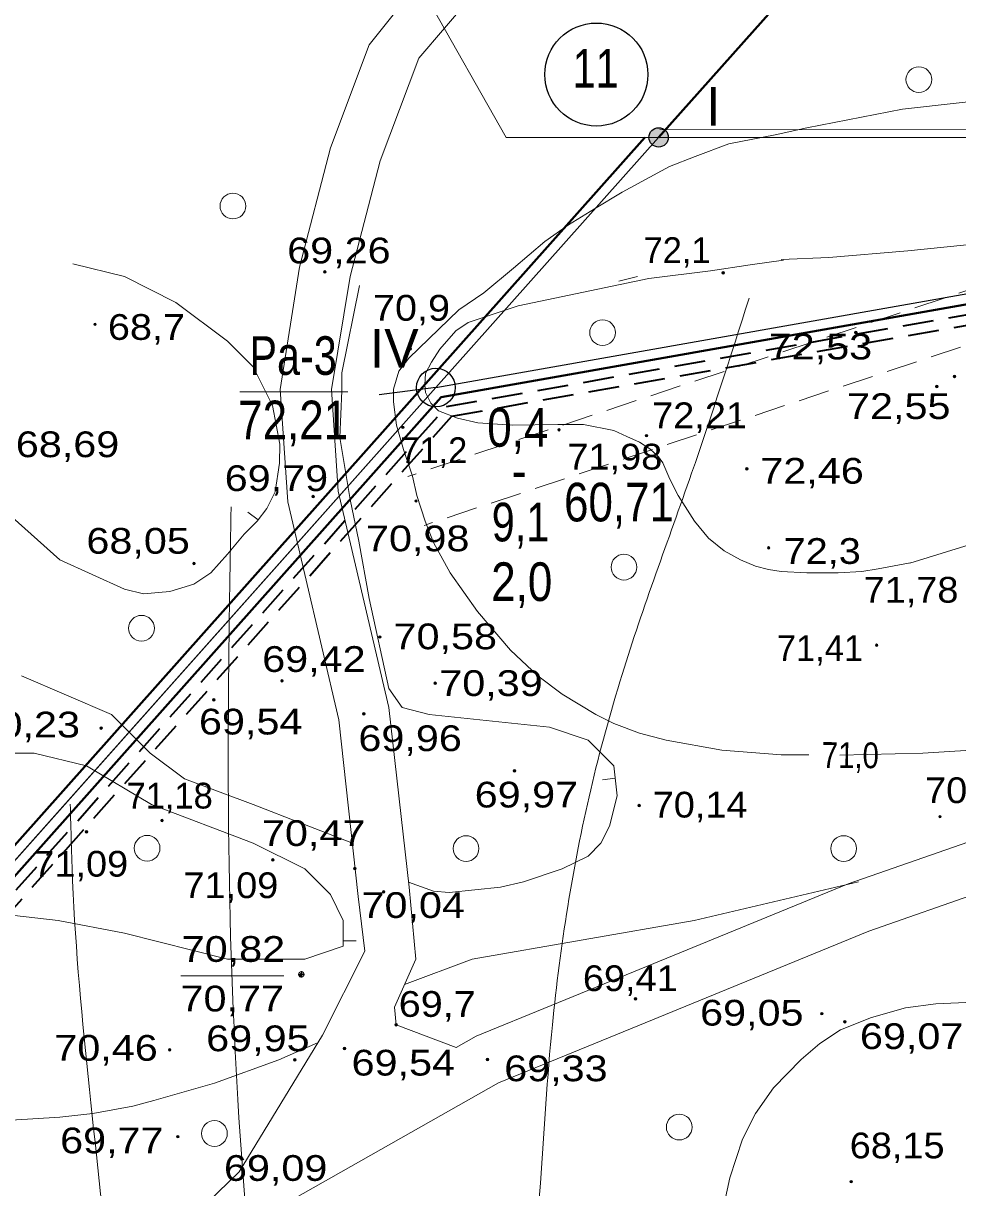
# Model space of a CAD drawing. Extents: x 628176 to 629009, y 6439913 to 6440496.
# Drawn here: x 628361.2 to 628433.7, y 6440336.2 to 6440426.7 of the extents above; entities that cross this region are included whole.
import ezdxf
from ezdxf.enums import TextEntityAlignment as Align

# ---------------------------------------------------------------- set-up
doc = ezdxf.new("R2010")
doc.units = 0
doc.header["$LTSCALE"] = 0.8
doc.header["$PDMODE"] = 32
doc.header["$PDSIZE"] = 0.4
doc.linetypes.add('MEDIUM_DASHED', pattern=[4.5, 3, -1.5])
for name, color, linetype, lineweight in [('1', 7, 'Continuous', 13), ('10', 7, 'Continuous', 25), ('11', 7, 'Continuous', 13), ('12', 7, 'Continuous', 13), ('14', 7, 'Continuous', 25), ('16', 7, 'Continuous', 13), ('20', 7, 'Continuous', 40), ('21', 7, 'MEDIUM_DASHED', 35), ('3', 7, 'Continuous', 13), ('6', 7, 'Continuous', 13)]:
    doc.layers.add(name, color=color, linetype=linetype, lineweight=lineweight)

msp = doc.modelspace()

# ---------------------------------------------------------------- hatches: boundary and pattern name
at = {"layer": '1'}
for points in [[(628384.6556, 6440407.3657, 1), (628384.4556, 6440407.3657, 1)], [(628415.5893, 6440407.2985, 1), (628415.3893, 6440407.2985, 1)], [(628366.8202, 6440403.2956, 1), (628366.6202, 6440403.2956, 1)], [(628425.888, 6440402.6645, 1), (628425.688, 6440402.6645, 1)], [(628391.2986, 6440401.3946, 1), (628391.0986, 6440401.3946, 1)], [(628433.5561, 6440399.2515, 1), (628433.3561, 6440399.2515, 1)], [(628432.1769, 6440398.468, 1), (628431.9769, 6440398.468, 1)], [(628390.7286, 6440395.2981, 1), (628390.5286, 6440395.2981, 1)], [(628402.847, 6440395.112, 1), (628402.647, 6440395.112, 1)], [(628409.6313, 6440394.6528, 1), (628409.4313, 6440394.6528, 1)], [(628417.4364, 6440392.0781, 1), (628417.2364, 6440392.0781, 1)], [(628383.7494, 6440389.9172, 1), (628383.5494, 6440389.9172, 1)], [(628391.7433, 6440389.5751, 1), (628391.5433, 6440389.5751, 1)], [(628419.1251, 6440385.9317, 1), (628418.9251, 6440385.9317, 1)], [(628374.5019, 6440384.7205, 1), (628374.3019, 6440384.7205, 1)], [(628388.9275, 6440379.0094, 1), (628388.7275, 6440379.0094, 1)], [(628427.5111, 6440378.3701, 1), (628427.3111, 6440378.3701, 1)], [(628381.3358, 6440375.6103, 1), (628381.1358, 6440375.6103, 1)], [(628393.2398, 6440375.419, 1), (628393.0398, 6440375.419, 1)], [(628376.0368, 6440374.1368, 1), (628375.8368, 6440374.1368, 1)], [(628387.6971, 6440373.0504, 1), (628387.4971, 6440373.0504, 1)], [(628367.2906, 6440371.9388, 1), (628367.0906, 6440371.9388, 1)], [(628399.3871, 6440368.615, 1), (628399.1871, 6440368.615, 1)], [(628409.0693, 6440365.9186, 1), (628408.8693, 6440365.9186, 1)], [(628372.0228, 6440364.7648, 1), (628371.8228, 6440364.7648, 1)], [(628432.4266, 6440365.061, 1), (628432.2266, 6440365.061, 1)], [(628366.1523, 6440363.8858, 1), (628365.9523, 6440363.8858, 1)], [(628380.6172, 6440361.6969, 1), (628380.4172, 6440361.6969, 1)], [(628386.9911, 6440361.0246, 1), (628386.7911, 6440361.0246, 1)], [(628389.233, 6440359.2215, 1), (628389.033, 6440359.2215, 1)], [(628382.7615, 6440352.6918, 1), (628382.5615, 6440352.6918, 1)], [(628382.8372, 6440352.8118, 1), (628382.6372, 6440352.8118, 1)], [(628408.7874, 6440350.9089, 1), (628408.5874, 6440350.9089, 1)], [(628423.26, 6440349.7561, 1), (628423.06, 6440349.7561, 1)], [(628425.0383, 6440349.1318, 1), (628424.8383, 6440349.1318, 1)], [(628390.1948, 6440348.8964, 1), (628389.9948, 6440348.8964, 1)], [(628372.6184, 6440346.9498, 1), (628372.4184, 6440346.9498, 1)], [(628386.1926, 6440347.0472, 1), (628385.9926, 6440347.0472, 1)], [(628397.2867, 6440346.1959, 1), (628397.0867, 6440346.1959, 1)], [(628382.3265, 6440346.1721, 1), (628382.1265, 6440346.1721, 1)], [(628373.2407, 6440340.2028, 1), (628373.0407, 6440340.2028, 1)], [(628425.5388, 6440336.7091, 1), (628425.3388, 6440336.7091, 1)]]:
    msp.add_hatch(color=256, dxfattribs=at).paths.add_polyline_path(points)
at = {"layer": '10'}
msp.add_hatch(color=256, dxfattribs=at).paths.add_polyline_path([(628411.2339, 6440417.8164, 1), (628409.7339, 6440417.8164, 1)])

# ---------------------------------------------------------------- linework, layer by layer
at = {"layer": '1'}
for p, q in [((628388, 6440425), (628396, 6440435)), ((628399.08, 6440432.45), (628391.87, 6440423.98)), ((628386.52, 6440407), (628385.09, 6440398.24)), ((628385.09, 6440398.24), (628385.6, 6440390.34)), ((628385.6, 6440390.34), (628389.54, 6440373.53)), ((628381.69, 6440389.5), (628385.66, 6440372.57)), ((628389.54, 6440373.53), (628391.1, 6440359.57)), ((628385.66, 6440372.57), (628387.16, 6440358.87)), ((628447.23, 6440367.53), (628425.19, 6440359.83)), ((628448.37, 6440363.69), (628426.81, 6440356.17)), ((628391.1, 6440359.57), (628391.62, 6440354)), ((628425.19, 6440359.83), (628407.95, 6440352.77)), ((628387.16, 6440358.87), (628387.68, 6440354.6)), ((628426.81, 6440356.17), (628409.43, 6440349.05)), ((628387.68, 6440354.6), (628384.39, 6440348.09)), ((628391.62, 6440354), (628389.97, 6440350.27)), ((628373.37, 6440352.69), (628381.37, 6440352.69)), ((628382.74, 6440352.81), (628382.49, 6440352.81)), ((628382.74, 6440352.81), (628382.74, 6440353.06)), ((628382.74, 6440352.81), (628382.74, 6440352.56)), ((628382.74, 6440352.81), (628382.99, 6440352.81)), ((628407.95, 6440352.77), (628396.32, 6440348)), ((628389.97, 6440350.27), (628390.09, 6440348.9)), ((628409.43, 6440349.05), (628398.05, 6440344.39)), ((628390.09, 6440348.9), (628394.77, 6440347.12)), ((628384.39, 6440348.09), (628377.9, 6440337.48)), ((628394.77, 6440347.12), (628396.32, 6440348)), ((628398.05, 6440344.39), (628380.54, 6440334.48)), ((628372.24, 6440332), (628377.9, 6440337.48))]:
    msp.add_line(p, q, dxfattribs=at)
at = {"layer": '1', "linetype": 'MEDIUM_DASHED'}
for p, q in [((628439.49, 6440407.6), (628391.01, 6440391.47)), ((628440.75, 6440403.8), (628392.27, 6440387.68))]:
    msp.add_line(p, q, dxfattribs=at)
at = {"layer": '1'}
for points in [[(628382.59, 6440407.73), (628385, 6440417), (628388, 6440425)], [(628391.87, 6440423.98), (628388.87, 6440416), (628386.52, 6440407)], [(628382.59, 6440407.73), (628381.09, 6440398.24), (628381.69, 6440389.5)]]:
    msp.add_lwpolyline(points, dxfattribs=at)
for centre, radius in [((628430.688, 6440422.3012), 1), ((628377.428, 6440412.4844), 1), ((628384.5556, 6440407.3657), 0.1), ((628415.4893, 6440407.2985), 0.1), ((628366.7202, 6440403.2956), 0.1), ((628406.128, 6440402.6533), 1), ((628425.788, 6440402.6645), 0.1), ((628391.1986, 6440401.3946), 0.1), ((628433.4561, 6440399.2515), 0.1), ((628432.0769, 6440398.468), 0.1), ((628390.6286, 6440395.2981), 0.1), ((628402.747, 6440395.112), 0.1), ((628409.5313, 6440394.6528), 0.1), ((628417.3364, 6440392.0781), 0.1), ((628383.6494, 6440389.9172), 0.1), ((628391.6433, 6440389.5751), 0.1), ((628407.7893, 6440384.4394), 1), ((628419.0251, 6440385.9317), 0.1), ((628374.4019, 6440384.7205), 0.1), ((628370.3308, 6440379.6903), 1), ((628388.8275, 6440379.0094), 0.1), ((628427.4111, 6440378.3701), 0.1), ((628381.2358, 6440375.6103), 0.1), ((628393.1398, 6440375.419), 0.1), ((628375.9368, 6440374.1368), 0.1), ((628387.5971, 6440373.0504), 0.1), ((628367.1906, 6440371.9388), 0.1), ((628399.2871, 6440368.615), 0.1), ((628408.9693, 6440365.9186), 0.1), ((628371.9228, 6440364.7648), 0.1), ((628432.3266, 6440365.061), 0.1), ((628366.0523, 6440363.8858), 0.1), ((628370.7645, 6440362.6041), 1), ((628395.5275, 6440362.5813), 1), ((628424.8493, 6440362.5813), 1), ((628380.5172, 6440361.6969), 0.1), ((628386.8911, 6440361.0246), 0.1), ((628389.133, 6440359.2215), 0.1), ((628382.6615, 6440352.6918), 0.1), ((628382.7372, 6440352.8118), 0.1), ((628408.6874, 6440350.9089), 0.1), ((628423.16, 6440349.7561), 0.1), ((628424.9383, 6440349.1318), 0.1), ((628390.0948, 6440348.8964), 0.1), ((628372.5184, 6440346.9498), 0.1), ((628386.0926, 6440347.0472), 0.1), ((628397.1867, 6440346.1959), 0.1), ((628382.2265, 6440346.1721), 0.1), ((628412.0851, 6440340.9481), 1), ((628375.9918, 6440340.4503), 1), ((628373.1407, 6440340.2028), 0.1), ((628425.4388, 6440336.7091), 0.1)]:
    msp.add_circle(centre, radius, dxfattribs=at)
at = {"layer": '10'}
for centre, radius in [((628405.6476, 6440422.6988), 4), ((628410.4839, 6440417.8164), 0.75)]:
    msp.add_circle(centre, radius, dxfattribs=at)
at = {"layer": '11'}
for points in [[(628393.19, 6440398.39), (628410.48, 6440417.82), (628464.14, 6440417.8), (628544.36, 6440425.1), (628575.19, 6440427.91), (628595.11, 6440426.87)], [(628393.19, 6440398.39), (628479.31, 6440413.61), (628544.36, 6440425.1)], [(628497.5, 6440118.54), (628474.19, 6440080.39), (628272.25, 6440200.89), (628236.02, 6440221.83), (628393.19, 6440398.39)]]:
    msp.add_lwpolyline(points, dxfattribs=at)
msp.add_point((628382.74, 6440352.81), dxfattribs=at)
at = {"layer": '12'}
msp.add_line((628377.96, 6440398.05), (628386.36, 6440398.05), dxfattribs=at)
at = {"layer": '12', "lineweight": 25}
msp.add_circle((628393.1885, 6440398.3872), 1.5, dxfattribs=at)
at = {"layer": '14'}
for q in [(628326.62, 6440323.6), (628388.77, 6440397.83)]:
    msp.add_line((628393.19, 6440398.39), q, dxfattribs=at)
for points in [[(628393.19, 6440398.39), (628479.31, 6440413.61), (628544.36, 6440425.1)], [(628412.22, 6440419.76), (628410.48, 6440417.82), (628393.19, 6440398.39)]]:
    msp.add_lwpolyline(points, dxfattribs=at)
at = {"layer": '16'}
for points in [[(628417.51, 6440405.33), (628413.04, 6440391.73), (628407.64, 6440376.09), (628405.21, 6440367.15), (628402.23, 6440348.89), (628401.3, 6440336.6), (628400.74, 6440326.92), (628400.74, 6440316.86), (628400.56, 6440301.21), (628402.42, 6440288.73), (628405.96, 6440280.54), (628414.34, 6440271.97), (628424.59, 6440263.4), (628430.76, 6440257.95)], [(628377.28, 6440389.13), (628377.09, 6440364.17), (628380.07, 6440319.28), (628382.3, 6440305.31), (628388.08, 6440283.33), (628396.46, 6440266.57), (628400.19, 6440262.1), (628404.68, 6440258.52)], [(628364.8, 6440366.03), (628364.98, 6440360.07), (628367.96, 6440327.66), (628369.27, 6440306.05), (628369.93, 6440288.62)]]:
    msp.add_spline(points, degree=3, dxfattribs=at)
at = {"layer": '20'}
for p, q in [((628410.48, 6440417.82), (628459.12, 6440472.45)), ((628235.32, 6440222.24), (628409.42, 6440417.82))]:
    msp.add_line(p, q, dxfattribs=at)
at = {"layer": '21'}
for p, q in [((628394.01, 6440396.91), (628478.27, 6440411.8)), ((628394.43, 6440396.17), (628476.73, 6440410.71))]:
    msp.add_line(p, q, dxfattribs=at)
at = {"layer": '21', "linetype": 'Continuous', "lineweight": 40}
for points in [[(628393.6, 6440397.65), (628479.44, 6440412.82), (628544.47, 6440424.31)], [(628320.39, 6440173.09), (628272.66, 6440201.58), (628237.27, 6440222.03), (628393.6, 6440397.65)]]:
    msp.add_lwpolyline(points, dxfattribs=at)
at = {"layer": '21'}
for points in [[(628321.72, 6440173.24), (628273.06, 6440202.27), (628238.52, 6440222.23), (628394.01, 6440396.91)], [(628321.66, 6440174.2), (628273.47, 6440202.96), (628239.77, 6440222.44), (628394.43, 6440396.17)]]:
    msp.add_lwpolyline(points, dxfattribs=at)
at = {"layer": '3'}
for p, q in [((628429.84, 6440409), (628448.92, 6440411)), ((628407.4, 6440406.65), (628408.84, 6440407)), ((628380.51, 6440397), (628379, 6440400)), ((628381.04, 6440392.52), (628380.72, 6440390.29)), ((628380.06, 6440389), (628380.72, 6440390.29)), ((628391.71, 6440390), (628392.36, 6440388)), ((628378.59, 6440388.72), (628379.38, 6440388.11)), ((628437.31, 6440387), (628429.98, 6440384.75)), ((628422.15, 6440369.86), (628420, 6440369.87)), ((628431, 6440370), (628424.54, 6440369.84)), ((628406.12, 6440367.92), (628407.11, 6440368.04)), ((628393, 6440359.26), (628391.06, 6440359.98)), ((628393, 6440359.26), (628394.21, 6440359.18)), ((628387, 6440355.41), (628386, 6440355.41)), ((628381, 6440346.17), (628384, 6440347.48)), ((628376, 6440344.36), (628381, 6440346.17)), ((628364, 6440341.72), (628360.22, 6440341.49))]:
    msp.add_line(p, q, dxfattribs=at)
for points in [[(628422, 6440418.57), (628429.42, 6440420), (628438.21, 6440421), (628450.1, 6440422), (628459.07, 6440423), (628466.71, 6440424), (628472.14, 6440425), (628475.51, 6440426), (628477.87, 6440427), (628479.64, 6440428), (628483.9, 6440431), (628486.91, 6440433), (628490.26, 6440435), (628497.84, 6440439), (628499.78, 6440440), (628501.87, 6440441), (628506.4, 6440443), (628526.88, 6440451), (628533.59, 6440454), (628545.23, 6440460), (628547.31, 6440461)], [(628422, 6440418.57), (628419.52, 6440418.01), (628415.92, 6440417.32), (628413.31, 6440416.32), (628411.32, 6440415.56), (628407.64, 6440413.56), (628405.49, 6440412.26), (628403.49, 6440411.03), (628401.65, 6440409.73), (628399.2, 6440407.66), (628396.9, 6440405.74), (628394.98, 6440404.43), (628391.08, 6440400.66), (628390.32, 6440399.65), (628389.89, 6440398.25)], [(628420, 6440408.34), (628423.7, 6440408.5), (628429.84, 6440409)], [(628379, 6440400), (628377, 6440402), (628373, 6440405), (628369, 6440407), (628365, 6440408)], [(628408, 6440394.59), (628407.01, 6440395.05), (628404.65, 6440395.52), (628402.65, 6440395.52), (628399.11, 6440395.47), (628396.45, 6440395.64), (628394.86, 6440396), (628393.39, 6440396.59), (628392.8, 6440397.18), (628392.38, 6440398), (628392.32, 6440398.59), (628392.38, 6440399.48), (628392.85, 6440400.36), (628393.5, 6440401.37), (628394.74, 6440402.78), (628395.69, 6440403.43), (628399.58, 6440404.73), (628409.73, 6440406.85), (628414.51, 6440407.44), (628417.58, 6440407.91), (628420.17, 6440408.27)], [(628387.21, 6440386.46), (628386.54, 6440389.68), (628385.72, 6440394.52), (628385.89, 6440398.12), (628385.89, 6440399.54), (628387.25, 6440406.32)], [(628389.89, 6440398.25), (628389.9, 6440397.29), (628390.14, 6440395.47), (628390.67, 6440393.58), (628391.38, 6440391.51), (628391.71, 6440390)], [(628381.04, 6440392.52), (628381.08, 6440394), (628380.51, 6440397)], [(628430, 6440384.76), (628427.52, 6440384.3), (628426.25, 6440384.1), (628424.42, 6440384), (628422, 6440384), (628420, 6440384.1), (628419, 6440384.26), (628418, 6440384.51), (628416.84, 6440385), (628415.58, 6440385.71), (628414.36, 6440386.7), (628413.26, 6440388), (628412, 6440390), (628411.36, 6440391.26), (628410.82, 6440392.55), (628410.48, 6440393), (628409.81, 6440393.64), (628409, 6440394.14), (628408, 6440394.59)], [(628380.06, 6440389), (628379.3, 6440388), (628378.29, 6440387), (628377, 6440385.44), (628375.71, 6440384), (628374.4, 6440383.12), (628372.52, 6440382.55), (628370.48, 6440382.37), (628369, 6440382.74), (628364, 6440385), (628359.54, 6440389), (628356, 6440391), (628353, 6440392)], [(628420, 6440369.87), (628415.4, 6440370.22), (628411.07, 6440371), (628409, 6440371.55), (628407, 6440372.29), (628405.61, 6440373), (628403, 6440374.56), (628401.09, 6440376), (628398.97, 6440378), (628396.43, 6440381), (628394.29, 6440384), (628393, 6440386.35), (628392.36, 6440388)], [(628392.67, 6440373), (628390.57, 6440373.53), (628389.54, 6440375), (628388, 6440382), (628387.21, 6440386.46)], [(628361, 6440376), (628368, 6440373), (628371, 6440370), (628373.67, 6440368)], [(628407, 6440369), (628405, 6440371), (628402, 6440372), (628392.67, 6440373)], [(628431, 6440370), (628447.23, 6440371), (628464, 6440372.63)], [(628371.11, 6440366), (628366.05, 6440369), (628362, 6440370), (628360, 6440370), (628354, 6440369.04), (628348.28, 6440367)], [(628400, 6440360), (628403, 6440361), (628405, 6440362), (628406, 6440363), (628406.67, 6440364.32), (628407.26, 6440366.68), (628407, 6440369)], [(628373.67, 6440368), (628379, 6440366), (628386.71, 6440363)], [(628383, 6440361), (628385, 6440359), (628386, 6440357), (628386, 6440355), (628383, 6440354), (628377, 6440354), (628369, 6440356), (628363.85, 6440357), (628355, 6440358), (628351, 6440357), (628348, 6440358), (628346, 6440360), (628346, 6440363), (628347, 6440366), (628348.28, 6440367)], [(628383, 6440361), (628378.99, 6440363), (628371.11, 6440366)], [(628390.75, 6440352.03), (628396, 6440354), (628413.25, 6440357), (628426, 6440360)], [(628400, 6440360), (628398.2, 6440359.57), (628394.21, 6440359.18)], [(628421.56, 6440346.2), (628423, 6440347.43), (628424.61, 6440348.51), (628427, 6440349.45), (628429.65, 6440350.22), (628432, 6440350.52), (628443.09, 6440351), (628457, 6440352), (628466, 6440351)], [(628421.56, 6440346.2), (628419.39, 6440344), (628418, 6440342), (628417, 6440340), (628416, 6440337), (628415.14, 6440332.94), (628414, 6440329.43)], [(628364, 6440341.72), (628366.54, 6440342), (628369.66, 6440342.58), (628371.29, 6440343), (628376, 6440344.36)]]:
    msp.add_lwpolyline(points, dxfattribs=at)
at = {"layer": '6'}
for p, q in [((628367.72, 6440472.45), (628398.64, 6440417.82)), ((628398.64, 6440417.82), (628410.48, 6440417.82))]:
    msp.add_line(p, q, dxfattribs=at)
msp.add_lwpolyline([(628410.58, 6440418.42), (628464.11, 6440418.4), (628464.94, 6440418.48)], dxfattribs=at)

# ---------------------------------------------------------------- texts
at = {"layer": '1'}
for s, width, p in [('69,26', 1.2, (628381.64, 6440408.03)), ('70,9', 1.15, (628388.3, 6440403.58)), ('68,7', 1.15, (628367.72, 6440402.09)), ('72,53', 1.2, (628419.03, 6440400.57)), ('72,55', 1.2, (628425.11, 6440395.94)), ('72,21', 1.1, (628409.98, 6440395.23)), ('68,69', 1.2, (628360.57, 6440392.98)), ('71,98', 1.1, (628403.4, 6440392.02)), ('72,46', 1.2, (628418.38, 6440390.92)), ('69,79', 1.2, (628376.79, 6440390.35)), ('68,05', 1.2, (628366.05, 6440385.48)), ('70,98', 1.2, (628387.76, 6440385.67)), ('72,3', 1.15, (628420.19, 6440384.69)), ('71,78', 1.1, (628426.4, 6440381.68)), ('70,58', 1.2, (628389.9, 6440378.06)), ('69,42', 1.2, (628379.7, 6440376.3)), ('70,39', 1.2, (628393.45, 6440374.43)), ('69,54', 1.2, (628374.79, 6440371.44)), ('70,23', 1.2, (628357.52, 6440371.21)), ('69,96', 1.2, (628387.17, 6440370.15)), ('70,17', 1.1, (628431.17, 6440366.11)), ('69,97', 1.2, (628396.2, 6440365.77)), ('70,14', 1.1, (628410.02, 6440364.99)), ('70,47', 1.2, (628379.68, 6440362.78)), ('71,09', 1.1, (628361.93, 6440360.4)), ('71,09', 1.1, (628373.59, 6440358.73)), ('70,04', 1.2, (628387.41, 6440357.19)), ('70,82', 1.2, (628373.45, 6440353.78)), ('69,41', 1.1, (628404.6, 6440351.51)), ('70,77', 1.2, (628373.36, 6440349.93)), ('69,7', 1.15, (628390.3, 6440349.51)), ('69,05', 1.2, (628413.7, 6440348.83)), ('69,07', 1.2, (628426.11, 6440347.01)), ('70,46', 1.2, (628363.56, 6440346.1)), ('69,95', 1.2, (628375.35, 6440346.84)), ('69,54', 1.2, (628386.64, 6440344.95)), ('69,33', 1.2, (628398.49, 6440344.51)), ('69,77', 1.2, (628364.01, 6440338.91)), ('68,15', 1.1, (628425.32, 6440338.52)), ('69,09', 1.2, (628376.73, 6440336.77))]:
    msp.add_text(s, height=2, dxfattribs=dict(at, width=width)).set_placement(p)
for s, p in [('72,1', (628409.31, 6440408.06)), ('71,2', (628390.42, 6440392.52)), ('71,41', (628419.66, 6440377.15)), ('71,18', (628369.17, 6440365.69))]:
    msp.add_text(s, height=2, dxfattribs=at).set_placement(p)
at = {"layer": '10', "width": 0.8}
msp.add_text('11', height=3, dxfattribs=at).set_placement((628405.59, 6440421.68), align=Align.CENTER)
at = {"layer": '12'}
for s, width, p in [('Pa-3', 0.8, (628382.1, 6440399.37)), ('72,21', 0.85, (628382.105, 6440394.37)), ('0,4', 0.85, (628399.545, 6440393.79)), ('-', 0.85, (628399.655, 6440390.44)), ('60,71', 0.85, (628407.405, 6440387.99)), ('9,1', 0.8, (628399.755, 6440386.44)), ('2,0', 0.85, (628399.855, 6440381.81))]:
    msp.add_text(s, height=3, dxfattribs=dict(at, width=width)).set_placement(p, align=Align.CENTER)
at = {"layer": '14'}
for s, p in [('I', (628414.73, 6440418.72)), ('IV', (628389.955, 6440399.94))]:
    msp.add_text(s, height=3, dxfattribs=at).set_placement(p, align=Align.CENTER)
at = {"layer": '3', "width": 0.85}
msp.add_text('71,0', height=2, rotation=359.571, dxfattribs=at).set_placement((628423.15, 6440368.85))

doc.saveas('drawing.dxf')
